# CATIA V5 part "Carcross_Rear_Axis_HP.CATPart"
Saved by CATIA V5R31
Part number: Carcross_Rear_Axis_HP
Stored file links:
  R:\Din II\Pfinal\CAD\Carcross_Rear_Axis_HP.CATPart
  R:\Din II\Pfinal\CAD\Carcross_Front_Axis_HP.CATPart
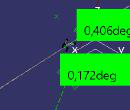
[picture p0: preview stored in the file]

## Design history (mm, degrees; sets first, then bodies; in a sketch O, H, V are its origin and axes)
AxisSystem1: origin (0, 0, 0), X (1, 0, 0), Y (0, 1, 0), Z (0, 0, 1)
Set1 "Rear_Axis"
  Set2 "Left_wheel"
    Set3 "Lower_arm"
      Set4 "Lower_arm_C"
        Point1 "A": (1620, -134, 400), in AxisSystem1
        Point2 "B": (1970, -582, 256), in AxisSystem1
        Point3 "C": (2314, -91, 295), in AxisSystem1
        Line1: type PtPt, FirstPoint Point1, SecondPoint Point2
        Line2: type PtPt, FirstPoint Point3, SecondPoint Point2
        Plane1 "Lower_plane": type 3Points, Element1 Point1, Element2 Point2, Element3 Point3
      Join1 "Lower_arm": Elements (Line1; Line2)
    Set5 "Upper_arm"
      Set6 "Upper_arm_C"
        Point4 "D": (1603, -130, 490), in AxisSystem1
        Point5 "E": (2045, -520, 414), in AxisSystem1
        Point6 "F": (2319, -131, 465), in AxisSystem1
        Line3: type PtPt, FirstPoint Point4, SecondPoint Point5
        Line4: type PtPt, FirstPoint Point6, SecondPoint Point5
        Plane2 "Upper_plane": type 3Points, Element1 Point4, Element2 Point5, Element3 Point6
      Join2 "Upper_arm": Elements (Line3; Line4)
    Set7 "IC_RollCenter"
      Intersect1 "IC_Line": ToIntersect1 Plane1, ToIntersect2 Plane2
      Intersect2 "IC_point_YZ": ToIntersect1 YZ plane of AxisSystem1, ToIntersect2 Intersect1
      Line5: type PtPt, FirstPoint Intersect5, SecondPoint Intersect2
      Intersect3 "RollCenter": ToIntersect1 ZX plane of AxisSystem1, ToIntersect2 Plane3
      Project1 "Tierod_Projection": ToProject Join3, Support YZ plane of AxisSystem1
      Intersect4 "IC_Aux_ZX": ToIntersect1 Intersect1, ToIntersect2 ZX plane of AxisSystem1
      Plane3 "IC_Plane": type 1Line1Pt, RefPoint Intersect5, Line Intersect1
      Line6 "Tie_rod_IC": type Tangency, RefPoint vertex of Project1, Curve Project1, Start 0, End 3157.608
    Set8 "tie_rod"
      Set9 "tie_rod_C"
        Point7 "In": (2318, -112, 355), in AxisSystem1
        Point8 "Out": (2121, -570, 270), in AxisSystem1
        Line7: type PtPt, FirstPoint Point7, SecondPoint Point8
      Join3 "tierod": Elements Line7
    Set10 "Strut"
      Set11 "Strut_C"
        Point9 "Down": (2047, -506, 458), in AxisSystem1
        Point10 "Up": (2147, -235, 926), in AxisSystem1
        Line8: type PtPt, FirstPoint Point9, SecondPoint Point10
      Join4 "Strut": Elements Line8
    Set12 "Wheel"
      Point11 "Wheel_Center": (2040, -615, 315), in AxisSystem1
      Line9: type PtDir, RefPoint Point11, Direction (0, 0, 1), Start -400, End 400
      Intersect5 "Wheel_Floor": ToIntersect1 Line9, ToIntersect2 XY plane of AxisSystem1
    Set13 "Mangeta"
      Set14 "Mangeta_C"
        Line10: type PtPt, FirstPoint Point2, SecondPoint Point11
        Line11: type PtPt, FirstPoint Point8, SecondPoint Point11
        Line12: type PtPt, FirstPoint Point5, SecondPoint Point11
        Plane4 "Plane_outers_original": type 3Points, Element1 Point2, Element2 Point5, Element3 Point8
        Plane5 "Plane_outers_original_WC": type OffsetPt, RefPlane Plane4, RefPoint Point11
        Intersect6 "Toe_original": ToIntersect1 Plane5, ToIntersect2 XY plane of AxisSystem1
        Intersect7 "Camber_original": ToIntersect1 Plane5, ToIntersect2 YZ plane of AxisSystem1
    Set15 "Drive_shaft"
      Set16 "Drive_shaft_C"
        Point12 "In": (2155, -172, 362), in AxisSystem1
        Line13: type PtPt, FirstPoint Point12, SecondPoint Point11
      Join5 "Drive_shaft": Elements Line13
    Set17 "Setup"
      Set18 "Setup_C"
        Set19 "Tierod"
          Line14 "tierod_extension": type Tangency, RefPoint Point8, Curve Join3, Start 0, End 1.25
          Point13 "tierod_point_extension": type OnCurve, Support Line14, Ratio 1
        Set20 "LCA"
          Line15 "lca_extension": type Tangency, RefPoint Point2, Curve Line17, Start 0, End 0.01
          Point14 "lca_point_extension": type OnCurve, Support Line15, Ratio 1
          Line16 "front_rear": type PtPt, FirstPoint Point1, SecondPoint Point3
          Point15 "half_front_rear": type OnCurve, Support Line16, Ratio 0.5
          Line17 "Dirct_axis": type PtPt, FirstPoint Point15, SecondPoint Point2
        Set21 "UCA"
          Line18 "uca_extension": type Tangency, RefPoint Point5, Curve Line20, Start 0, End 0.01
          Point16 "uca_point_extension": type OnCurve, Support {inverselocal InverseElem Line18}, Ratio 1
          Line19 "line_front_rear": type PtPt, FirstPoint Point4, SecondPoint Point6
          Point17 "mipoint_front_rear": type OnCurve, Support Line19, Ratio 0.5
          Line20 "HP_direction": type PtPt, FirstPoint Point17, SecondPoint Point5
        Set22 "Mangueta"
          Line21 "lca_wc": type PtPt, FirstPoint Point14, SecondPoint Point11
          Line22 "tierod_wc": type PtPt, FirstPoint Point13, SecondPoint Point11
          Line23 "uca_wc": type PtPt, FirstPoint Point16, SecondPoint Point11
          Plane6 "Plane_outers": type 3Points, Element1 Point13, Element2 Point14, Element3 Point16
          Plane7 "Plane_outers_WC": type OffsetPt, RefPlane Plane6, RefPoint Point11
          Intersect8 "Toe_setup": ToIntersect1 Plane7, ToIntersect2 XY plane of AxisSystem1
          Intersect9 "Camber_setup": ToIntersect1 Plane7, ToIntersect2 YZ plane of AxisSystem1
  Set23 "Right_Wheel"
    MultiSel1
Body1 (main body)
